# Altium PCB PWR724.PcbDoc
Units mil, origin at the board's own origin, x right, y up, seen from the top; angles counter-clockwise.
Board outline 2700 x 2000 mil, 2 copper layers (Top Layer, Bottom Layer), stack 62 mil thick; 55 components, 31 nets, 127 pads, 0 vias.
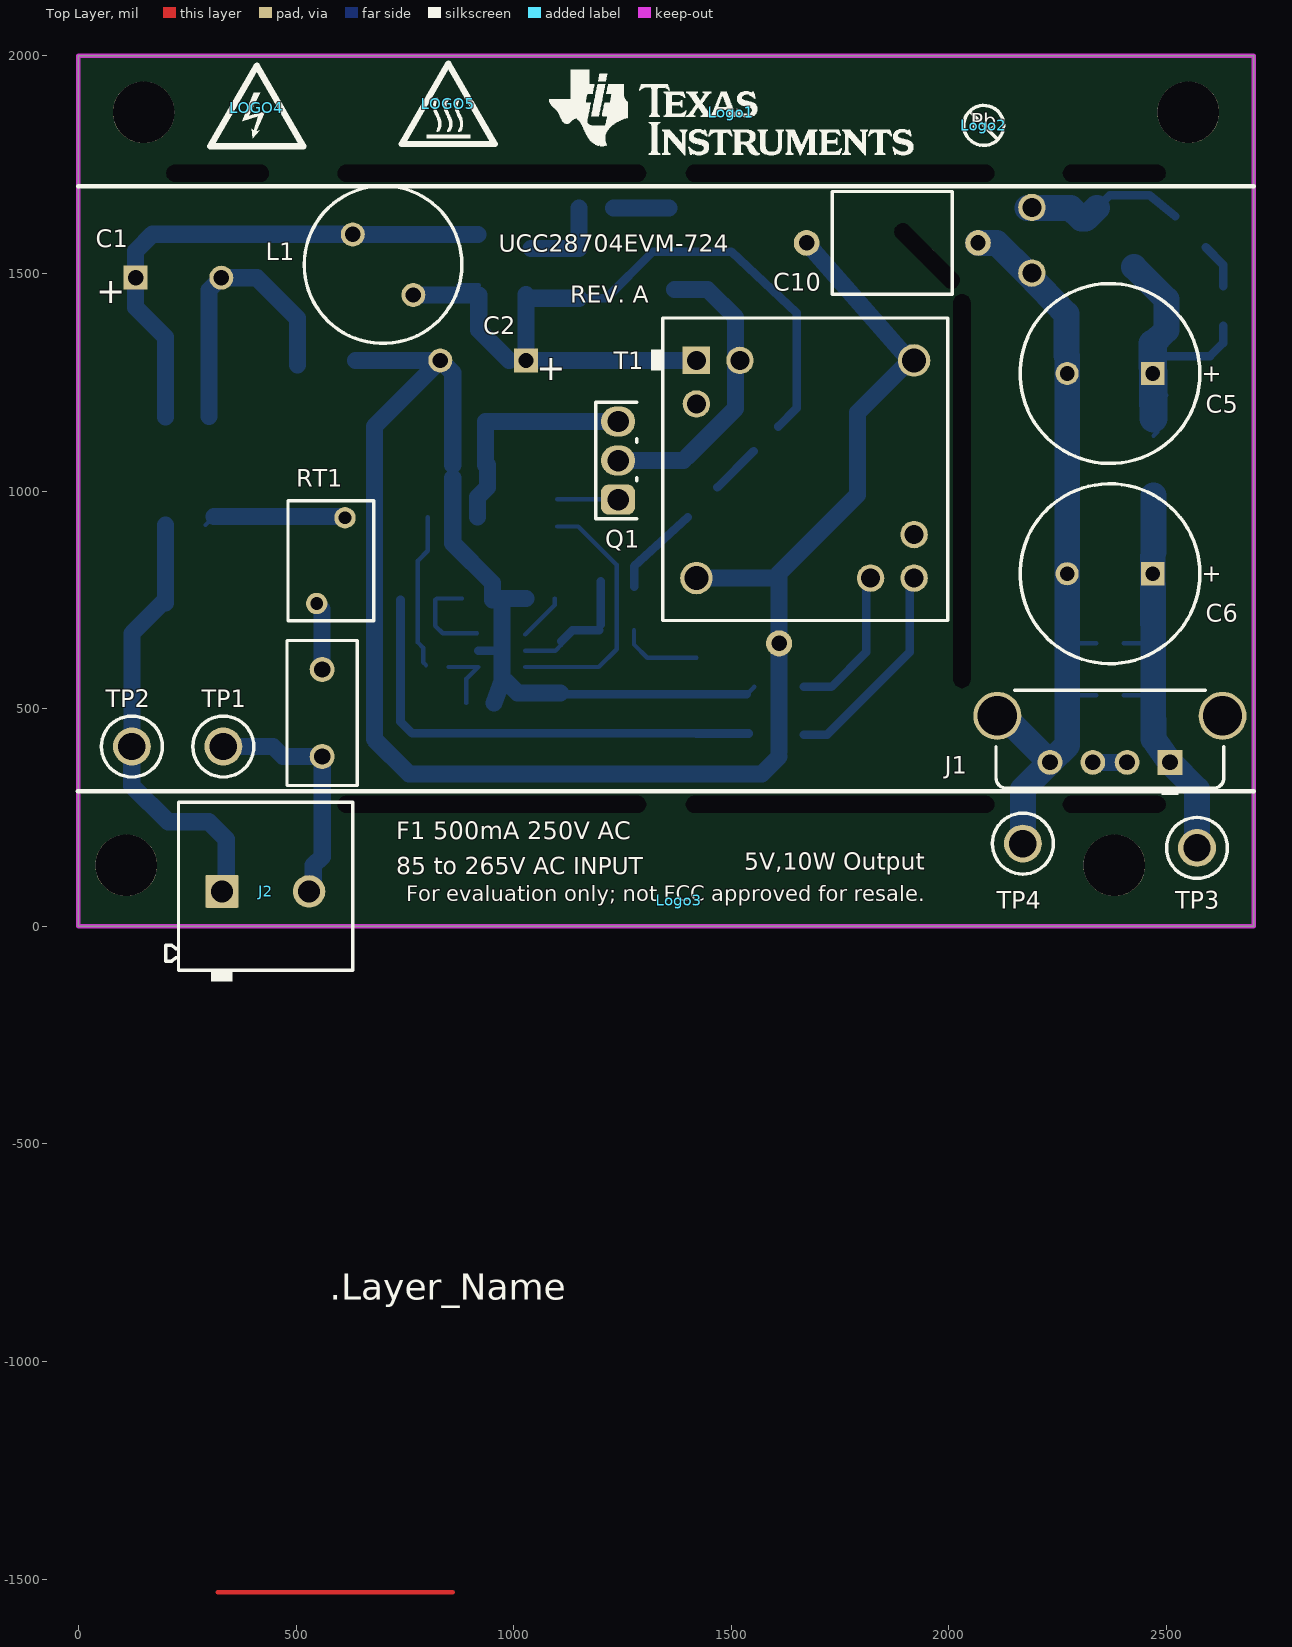
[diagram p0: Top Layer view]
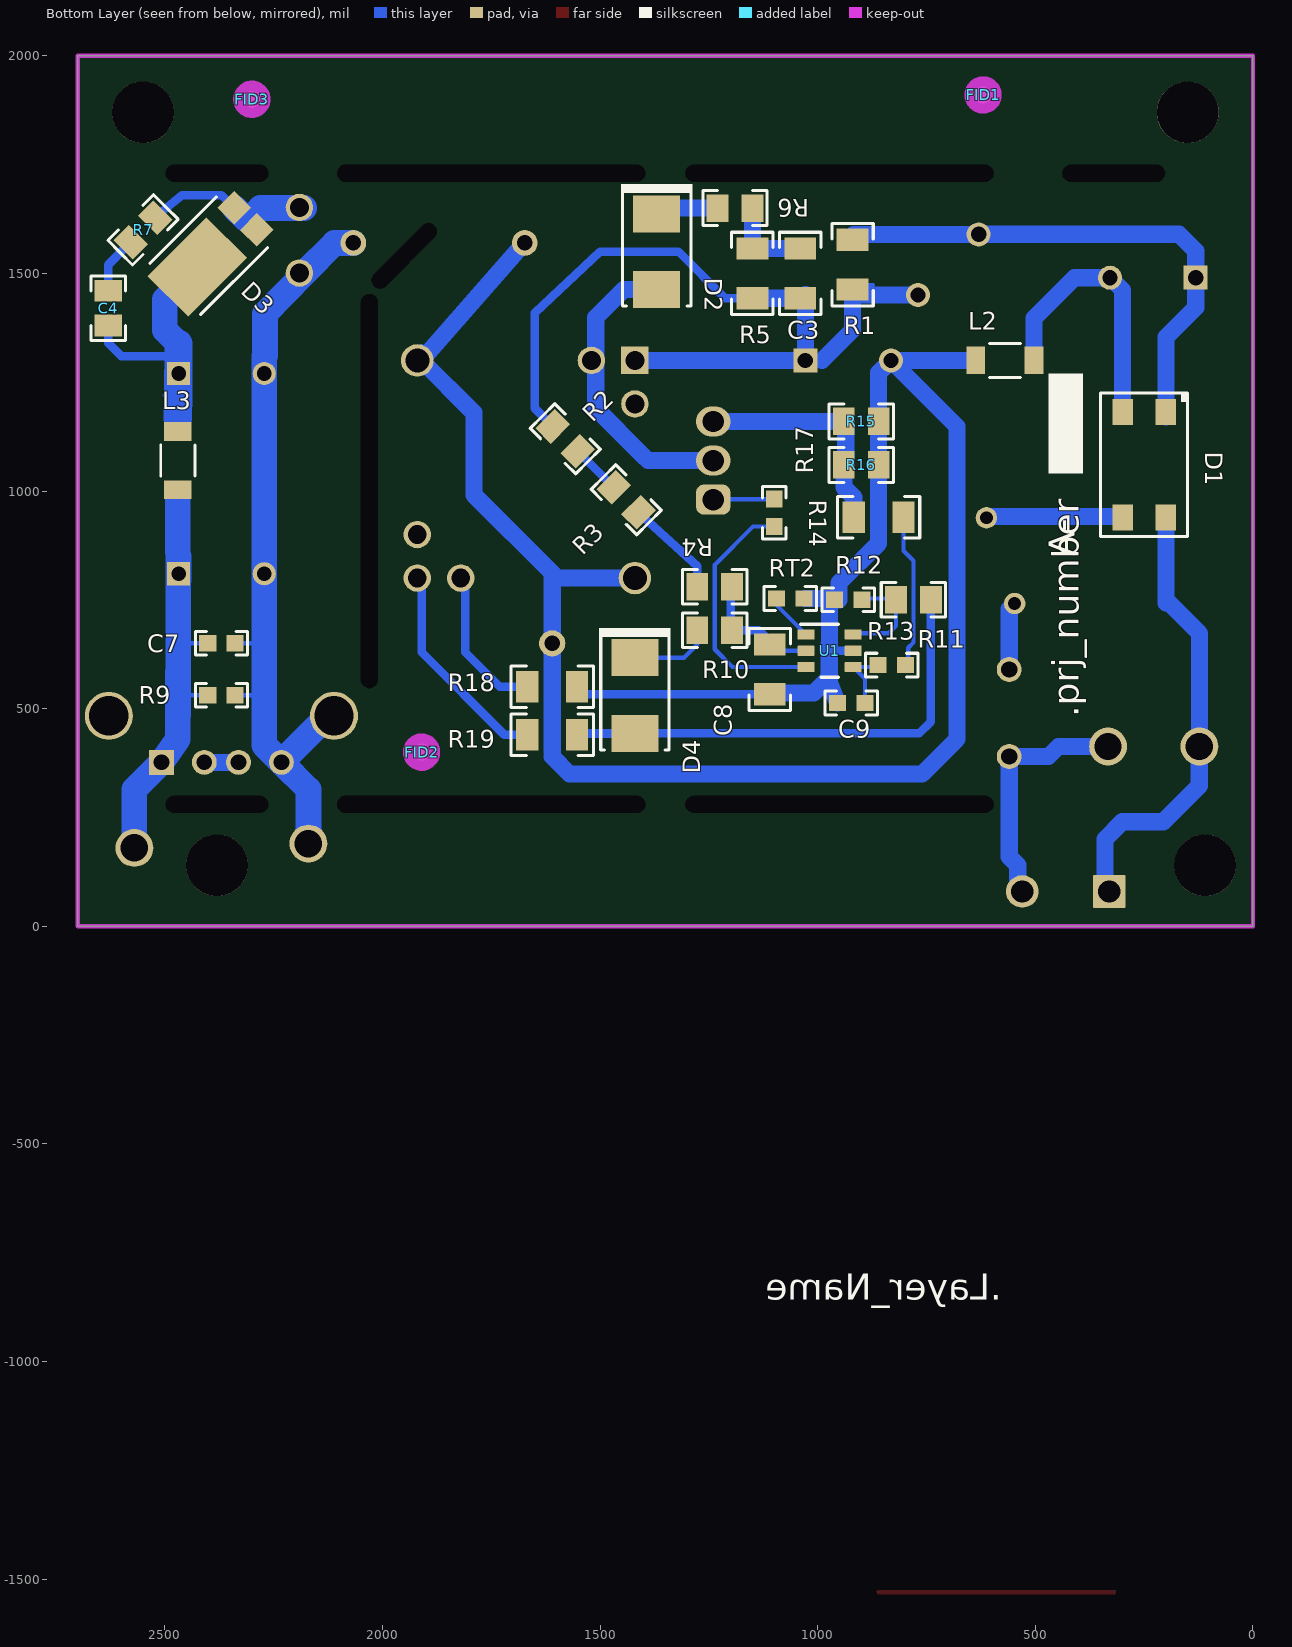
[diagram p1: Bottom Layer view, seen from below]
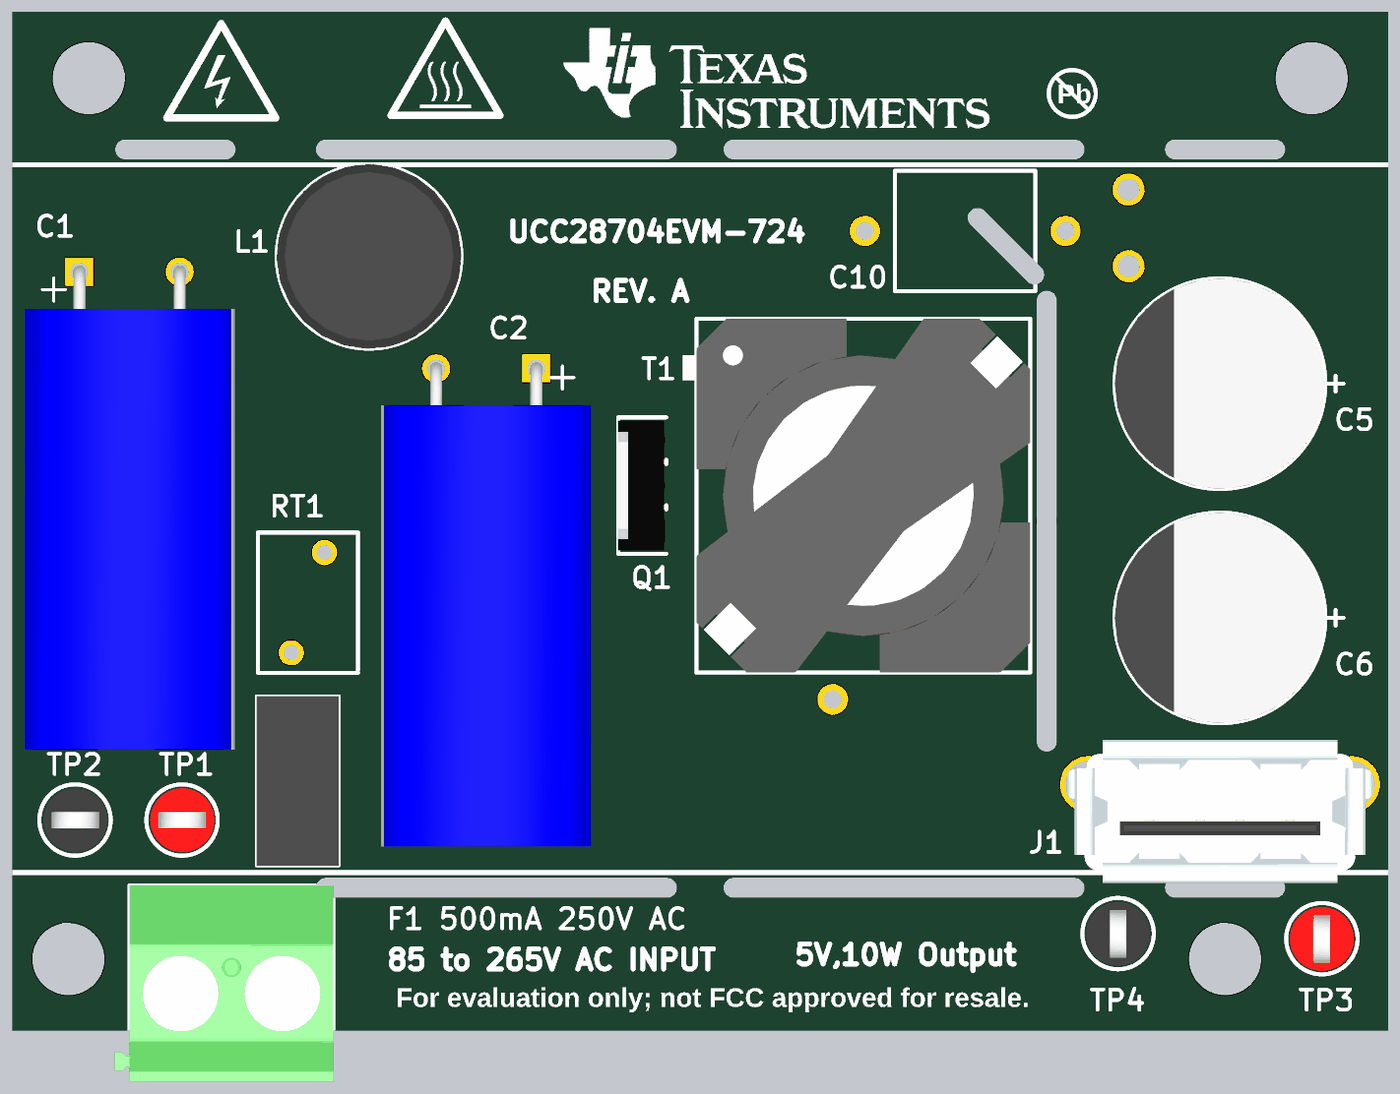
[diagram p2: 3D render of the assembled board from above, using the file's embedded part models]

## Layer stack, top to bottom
Top Solder: solder mask 0.4, Solder Resist, Dk 3.5
Top Layer: signal copper 2.8
Dielectric1: core 56.4, FR-4, Dk 4.8
Bottom Layer: signal copper 2.8
Bottom Solder: solder mask 0.4, Solder Resist, Dk 3.5

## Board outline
0,0 0,2000 2700,2000 2700,0

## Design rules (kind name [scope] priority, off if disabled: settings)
AcuteAngle [All] p1: minimum=4.50000000000000E+0001 checktracksonly=FALSE
AssemblyTestPointUsage [All] p1: valid=2
Clearance Clearance_Keepouts [((IsTrack Or IsArc) And Not InPoly) And IsFree and IsKeepOut vs ((IsTrack Or IsArc) And Not InPoly) And IsFree and IsKeepOut] p1: gap=0
Clearance Clearance_BoardEdge_MountingHoles [OnCopper and InComponentClass('Mounting Holes') vs IsKeepOut] p2: gap=40
Clearance Clearance_BoardEdge_Poly [OnCopper and InPoly vs IsKeepOut] p3: gap=25
Clearance Clearance_BoardEdge [OnCopper and Not InComponentClass('Logo') and not InComponentClass('FiducialMark') and not InRegion(1000,500,4000,800) and Not IsKeepout vs IsKeepOut] p4: gap=13.5
Clearance Clearance_Poly [InPolygon] p5: gap=25
Clearance [All] p6: gap=7.87
ComponentClearance ComponentClearance_MountingHoles_FiducialMarks [InComponentClass('Mounting Holes') vs InComponentClass('FiducialMark')] p1: gap=50 collisioncheckmode=3 verticalgap=10 showdistances=FALSE
ComponentClearance ComponentClearance_Shunt [InComponentClass('Header') vs InComponentClass('Shunt')] p2: gap=0 collisioncheckmode=3 verticalgap=0 showdistances=FALSE
ComponentClearance ComponentClearance_Logo [InComponentClass('Logo')] p3: gap=50 collisioncheckmode=3 verticalgap=10 showdistances=FALSE
ComponentClearance ComponentClearance_ScrewToNut [(HasFootprint('NY PMS 440 0025 PH')) vs (HasFootprint('Keystone_1902C'))] p4: gap=5 collisioncheckmode=3 verticalgap=10 showdistances=FALSE
ComponentClearance ComponentClearance_MountingHoles [InComponentClass('Mounting Holes')] p5: gap=250 collisioncheckmode=3 verticalgap=100000 showdistances=FALSE
ComponentClearance ComponentClearance_SmallPassives [HasFootprint('0201*') or HasFootprint('0402*') or HasFootprint('0508') or HasFootprint('0603*') or HasFootprint('0612') or HasFootprint('0805*') or HasFootprint('0815*') or HasFootprint('0830*') or HasFootprint('1206*') or HasFootprint('1210*') or HasFootprint('1808*') or HasFootprint('1812*') or HasFootprint('1825*') or HasFootprint('2010*') or HasFootprint('2220*') or HasFootprint('2225*') or HasFootprint('2512*') or HasFootprint('2728*') or HasFootprint('3518*') vs HasFootprint('0201*') or HasFootprint('0402*') or HasFootprint('0508') or HasFootprint('0603*') or HasFootprint('0612') or HasFootprint('0805*') or HasFootprint('0815*') or HasFootprint('0830*') or HasFootprint('1206*') or HasFootprint('1210*') or HasFootprint('1808*') or HasFootprint('1812*') or HasFootprint('1825*') or HasFootprint('2010*') or HasFootprint('2220*') or HasFootprint('2225*') or HasFootprint('2512*') or HasFootprint('2728*') or HasFootprint('3518*')] p6: gap=20 collisioncheckmode=3 verticalgap=10 showdistances=FALSE
ComponentClearance ComponentClearance_THtoSMT [IsThruComponent vs IsSMTComponent] p7: gap=100 collisioncheckmode=3 verticalgap=30 showdistances=FALSE
ComponentClearance ComponentClearance_THtoTH [IsThruComponent vs IsThruComponent] p8: gap=33 collisioncheckmode=3 verticalgap=30 showdistances=FALSE
ComponentClearance [All] p9: gap=40 collisioncheckmode=3 verticalgap=10 showdistances=FALSE
DiffPairsRouting [All] p1: maxlimit=100 minlimit=10 mostfreqgap=10 toplayer_minwidth=15 toplayer_maxwidth=15 toplayer_prefwidth=15 bottomlayer_minwidth=15 bottomlayer_maxwidth=15 bottomlayer_prefwidth=15 maxuncoupledlength=1000
FabricationTestPointUsage TestPointUsage [All] p1: valid=2 allowmultiple=FALSE
FabricationTestpoint Testpoint [All] p1: side=3 testpointundercomponent=TRUE minsize=40 maxsize=100 preferedsize=60 minholesize=0 maxholesize=40 preferedholesize=32 testpointgrid=1 allowsidetop=TRUE allowsidebottom=TRUE usegrid=TRUE gridtolerance=0.01
FanoutControl Fanout_LCC [IsLCC] p1: bgadir=Out bgaviamode=Centered fanoutstyle=Auto fanoutdirection=Alternating viagrid=1 // Fanout_LCC (Default Rule)
FanoutControl Fanout_BGA [IsBGA] p2: bgadir=Out bgaviamode=Centered fanoutstyle=Auto fanoutdirection=Alternating viagrid=1 // Fanout_BGA (Default Rule)
FanoutControl Fanout_Default [All] p4: bgadir=Out bgaviamode=Centered fanoutstyle=Auto fanoutdirection=Alternating viagrid=1 // Fanout_Default (Default Rule)
FanoutControl Fanout_Small [(CompPinCount < 5)] p5: bgadir=Out bgaviamode=Centered fanoutstyle=Auto fanoutdirection=OutThenIn viagrid=1 // Fanout_Small (Default Rule)
HoleSize [All] p1: absolutevalues=TRUE maxlimit=906 minlimit=8 maxpercent=80.000 minpercent=20.000
MinimumAnnularRing MinimumAnnularRing_ThermalPadVias [IsVia and InAnyComponent] p1: minimumring=5.91
MinimumAnnularRing [All] p2: minimumring=9
MinimumSolderMaskSliver MinimumSolderMaskSliver_Logo [InComponentClass('Logo') vs InComponentClass('Logo')] p1: minsoldermaskwidth=0.7
MinimumSolderMaskSliver [All] p2: minsoldermaskwidth=3.94
PlaneConnect [All] p1: planeconnectstyle=Relief reliefexpansion=10 reliefentries=4 reliefconductorwidth=10 reliefairgap=10
PolygonConnect [All] p1: connectstyle=Relief reliefconductorwidth=10 reliefentries=4 polygonreliefangle="90 Angle" airgapwidth=10
RoutingVias ThermalPadVias [IsVia and InAnyComponent] p1: holewidth=7.87 width=19.68 viastyle="Through Hole" minholewidth=7.87 minwidth=19.68 maxholewidth=12.99 maxwidth=23.62
RoutingVias [All] p2: holewidth=16 width=34 viastyle="Through Hole" minholewidth=7.87 minwidth=26 maxholewidth=40 maxwidth=65
SilkToBoardRegionClearance [Not ((IsComment or IsDesignator) And (Hide <> 'False')) and not InRegion(1000,500,4000,800)] p1:
SilkToSilkClearance SilkToSilkClearance_Pb-FreeLogo [(HasFootprint('Pb-Free_Overlay_Medium') OR HasFootprint('Pb-Free_Overlay_Small')) vs (HasFootprint('Pb-Free_Overlay_Medium') OR HasFootprint('Pb-Free_Overlay_Small'))] p1: silktosilkclearance=0
SilkToSilkClearance [All] p2: silktosilkclearance=4
SilkToSolderMaskClearance SilkToComonentPadClearance [IsPad and InAnycomponent] p1: minsilkscreentomaskgap=5 clearancetoexposedcopper=TRUE
SilkToSolderMaskClearance "Silk to Solder Mask Opening" [All] p2: minsilkscreentomaskgap=4 clearancetoexposedcopper=FALSE
SolderMaskExpansion [All] p1: expansion=1.97
UnpouredPolygon [All] p1: allowunpoured=FALSE
Width [All] p1: maxlimit=100 minlimit=6 preferedwidth=10 checkconnectedcopper=TRUE
14 further rules are at their usual default settings.

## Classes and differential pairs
component class FiducialMark: FID1 FID2 FID3
component class Logo: Logo1
component class PWR724_Hardware: !PCB FID1 FID2 FID3 Logo1 Logo2 Logo3 LOGO4 LOGO5

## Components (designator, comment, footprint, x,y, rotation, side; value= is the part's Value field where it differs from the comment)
C1 "UCS2G100MPD1TD" CAPPRD500W60D1000H2000_Horizontal_DOWN 230,1490 r0 top
C2 "UCS2G100MPD1TD" CAPPRD500W60D1000H2000_Horizontal_UP 930,1300 r180 top
C3 "GRM31A7U2J471JW31D" 1206 1040,1500 r90 bottom
C4 "08055A101JAT2A" 0805_HV 2630,1420 r90 bottom
C5 "PLF1C471MDO1" LF_1000x1300 2370,1270 r180 top
C6 "PLF1C471MDO1" LF_1000x1300 2370,810 r180 top
C7 "C1608X7R1E105K080AB" 0603 2370,650 r180 bottom
C8 "GRM319R71H334KA01D" 1206 1110,590.07 r270 bottom
C9 "06035A270JAT2A" 0603 923.01,513.07 r0 bottom
C10 "CD70-B2GA101KYNKA" CD_700x1100x700 1870,1570 r180 top
D1 "HD06-T" MiniDIP 250,1060 r270 bottom
D2 "MURS160-13-F" SMB 1370,1550 r270 bottom
D3 "SBRT15U50SP5-13" PowerDI5 2370,1570 r315 bottom
D4 "MURS160-13-F" SMB 1420,530 r270 bottom
"F1 500mA 250V AC" "RST 500" Fuse_RST 560,490 r270 top (schematic designator F1)
FID1 "Fiducial" Fiducial10-20 620,1910 r180 bottom
FID2 "Fiducial" Fiducial10-20 1910,400 r270 bottom
FID3 "Fiducial" Fiducial10-20 2300,1900 r270 bottom
J1 "923" Keystone_923 2370,430 r180 top
J2 "1715721" PhoenixContact_1715721 430,80 r0 top
L1 "RLB0914-471KL" RLB0914 700,1520 r315 top
L2 "742792121" 1206_190 570,1300 r0 bottom
L3 "742792121" 1206_190 2470,1070 r270 bottom
Logo1 "Texas Instruments" TI_Stacked_Overlay_Small 1500,1870 r0 top
Logo2 "Pb-Free Symbol" Pb-Free_Overlay_Small 2080,1840 r0 top
Logo3 "FCC disclaimer" FCC_disclaimer 1380,60 r0 top
LOGO4 "DANGER HIGH VOLTAGE" IEC_HighVoltage_Small 410,1880 r0 top
LOGO5 "CAUTION HOT SURFACE" IEC_HotSurface_Small 850,1890 r0 top
Q1 "STU7NM60N" IPAK 1240,1070 r90 top
R1 "CRCW12061K00FKEA" 1206 920,1520 r90 bottom
R2 "CRCW08055M11FKEA" 0805_HV 1580,1120 r45 bottom
R3 "CRCW08055M11FKEA" 0805_HV 1440,980 r45 bottom
R4 "CRCW08055M11FKEA" 0805_HV 1236.69,780 r0 bottom
R5 "CRCW1206511KFKEA" 1206 1150,1500 r270 bottom
R6 "CRCW080551R1FKEA" 0805_HV 1190,1650 r0 bottom
R7 "CRCW0805510KJNEA" 0805_HV 2550,1600 r315 bottom
R9 "CRCW06031K00FKEA" 0603 2370,531.08 r0 bottom
R10 "CRCW080520R0JNEA" 0805_HV 1236.69,680 r0 bottom
R11 "CRCW0805115KFKEA" 0805_HV 780,750.07 r180 bottom
R12 "CRCW060336K5FKEA" 0603 930,750 r180 bottom
R13 "RC0603FR-07715RL" 0603 830,600.07 r180 bottom
R14 "MCR18EZHJ000" 1206 860,940 r0 bottom
R15 "CRCW08052R15FKEA" 0805_HV 900,1160 r0 bottom
R16 "CRCW08052R15FKEA" 0805_HV 900,1060 r0 bottom
R17 "CRCW060310R0JNEAHP" 0603 1100,950 r90 bottom
R18 "MCR18EZHJ000" 1206 1610,550 r0 bottom
R19 "MCR18EZHJ000" 1206 1610,440 r0 bottom
RT1 "MF72-005D5" MF72D5 580,840 r90 top
RT2 "NTCG164KF104F" 0603 1063.01,753.07 r0 bottom
T1 "750315841" Wurth_750315841 1670,1050 r0 top
TP1 "5010" Keystone5010 333.01,413 r90 top
TP2 "5011" Keystone5011 123.01,413 r90 top
TP3 "5010" Keystone5010 2570,180 r0 top
TP4 "5011" Keystone5011 2170,190 r0 top
U1 "UCC28704DBVR-1" DBV0006A_N 972.7,633.07 r180 bottom

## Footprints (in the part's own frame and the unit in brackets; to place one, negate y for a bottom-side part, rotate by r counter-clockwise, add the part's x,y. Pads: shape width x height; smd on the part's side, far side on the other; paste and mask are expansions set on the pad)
0603 [mm] "0603 from SM-752 data"
  rect 1x0.95 smd: 1(-0.8,0) 2(0.8,0)
  silkscreen extent -1.52,-0.69 1.52,0.69, body extent -0.87,-0.47 0.87,0.47, height 1
0805_HV [mil] "0805 with 30mil clearance between pads"
  rect 50x63 smd: 1(-40,0) 2(40,0)
  silkscreen extent -74,-40 74,40, body extent -43,-29 43,29, height 57
1206 [mm] "1206 from SM-752 data"
  rect 1.3x1.85 smd: 1(-1.45,0) 2(1.45,0)
  silkscreen extent -2.4,-1.21 2.4,1.21, body extent -1.7,-0.9 1.7,0.9, height 1.35
1206_190 [mm] "1206_190"
  rect 1.1x1.6 smd: 1(-1.7,0) 2(1.7,0)
  silkscreen extent -0.9,-1 0.9,1, body extent -1.75,-0.95 1.75,0.95, height 1.9
CAPPRD500W60D1000H2000_Horizontal_DOWN [mm] "Nichicon"
  rect 1.4x1.4 hole 0.889: 1(-2.5,0)
  round 1.4 hole 0.889: 2(2.5,0)
  body extent -5.21,-23.85 5.24,0.3, height 10.49
CAPPRD500W60D1000H2000_Horizontal_UP [mm] "Nichicon"
  rect 1.4x1.4 hole 0.889: 1(-2.5,0)
  round 1.4 hole 0.889: 2(2.5,0)
  body extent -5.21,-0.3 5.23,23.85, height 10.49
CD_700x1100x700 [mm] "TDK"
  round 1.5 hole 0.9: 1(-5,0) 2(5,0)
  silkscreen extent -3.5,-3 3.5,3, body extent -5.3,-3 5.3,2.98, height 10.49
DBV0006A_N [mm] "SOT23, 6-Leads, Body 2.9x1.6mm, Pitch 0.95mm, Lead Span 2.8mm, IPC Medium Density"
  rrect17% 1x0.6 smd: 1(-1.375,0.95) 2(-1.375,0) 3(-1.375,-0.95) 4(1.375,-0.95) 5(1.375,0) 6(1.375,0.95)
  silkscreen extent -1.68,-1.55 0.5,1.55, body extent -1.42,-1.46 1.42,1.46, height 1.12
FCC_disclaimer [mil]
Fiducial10-20 [mm]
  round 1 smd mask+0.5: 1(0,0)
  Top Layer keep-out circle w1.178: c0,0 r0.5
Fuse_RST [mm] "Bel Fuse RST series May2012D"
  round 1.45 hole 0.95: 1(-2.54,0) 2(2.54,0)
  silkscreen extent -4.23,-2.05 4.23,2.05, body extent -4.22,-2.05 4.23,2.05, height 7.9
IEC_HighVoltage_Small [mil]
  silkscreen extent -107,-88 107,97
IEC_HotSurface_Small [mil]
  silkscreen extent -107,-93 107,92
IPAK [mm] "IPAK"
  rrect50% 1.75x2 hole 1.25: 1(-2.28,0)
  oval 1.75x2 hole 1.25: 2(0,0) 3(2.28,0)
  silkscreen extent -3.4,-1.1 3.4,1.3, body extent -3.25,-0.99 3.25,1.31, height 9.66
Keystone5010 [mil] "Keystone Multipurpose loops"
  round 87 hole 63: 1(0,0)
  silkscreen extent -70,-70 70,70, body extent -63,-63 63,62, height 319
Keystone5011 [mil] "Keystone Multipurpose loops"
  round 87 hole 63: 1(0,0)
  silkscreen extent -70,-70 70,70, body extent -63,-63 63,62, height 319
Keystone_923 [mm] "Connector, Receptacle, USB Type A, Vertical, TH"
  rect 1.45x1.45 hole 0.92: 1(-3.5,1.355)
  round 1.45 hole 0.92: 2(-1,1.355) 3(1,1.355) 4(3.5,1.355)
  round 2.8 hole 2.3: S1(-6.57,-1.355) S2(6.57,-1.355)
  silkscreen extent -6.65,-2.86 6.65,3.25, body extent -7.65,-3.56 7.65,3.56, height 14.38
LF_1000x1300 [mm] "THD, 2-Leads, 10 mm Dia, Height 13 mm, Pin Spacing 5 mm"
  rect 1.35x1.35 hole 0.85: 1(-2.5,0)
  round 1.35 hole 0.85: 2(2.5,0)
  silkscreen extent -5.25,-5.25 5.25,5.25, body extent -5.25,-5.24 5.25,5.24, height 13.51
MF72D5 [mm] "TH, 2-Leads, Dia 7mm"
  round 1.25 hole 0.75: 1(-2.5,0.825) 2(2.5,-0.825)
  silkscreen extent -3.5,-2.5 3.5,2.5, body extent -3.52,-2.5 3.48,2.5, height 11
MiniDIP [mm] "Land pattern created based on STEP model."
  rect 1.52x1.2 smd: 1(-3.075,1.25) 2(-3.075,-1.25) 3(3.075,-1.25) 4(3.075,1.25)
  silkscreen extent -4.19,-2.54 4.19,2.54, body extent -3.5,-2.45 3.5,2.45, height 2.75
Pb-Free_Overlay_Small [mil]
  silkscreen extent -46,-46 46,46
PhoenixContact_1715721 [mm] "Phoenix Contact 1715721 used on LM3445 design from Longmont"
  rrect5% 1.905x1.905 hole 1.3: 1(-2.54,0)
  round 1.9 hole 1.3: 2(2.54,0)
  silkscreen extent -5.82,-5.25 5.08,5.2, body extent -5.82,-4.6 5.08,5.2, height 14.2
PowerDI5 [mm] "Diodes Inc recommended land pattern, ap02001.pdf rev 60"
  rect 1.4x1.39 smd: 1(-1.991,0.92) 2(-1.991,-0.92)
  rect 4.86x3.36 smd: 3(1.991,0)
  silkscreen extent -1.7,-2.1 3.8,2.1, body extent -2.27,-2.02 4.33,2.03, height 1.17
RLB0914 [mm] "TH, 2-Leads, Dia 8.7mm, Pin Spacing 5mm"
  round 1.4 hole 0.9: 1(-2.5,0) 2(2.5,0)
  silkscreen extent -4.6,-4.6 4.6,4.6, body extent -4.6,-4.6 4.6,4.6, height 13
SMB [mil] "Molded Diode, 2-Leads, Body 5.4x3.6mm, IPC Medium Density, based on OnSemi component dimensions"
  rect 85x107.99 smd: 1(-87.01,0) 2(87.01,0)
  silkscreen extent -155,-82 125,82, body extent -106,-71 106,71, height 91
TI_Stacked_Overlay_Small [mil]
  silkscreen extent -418,-98 418,98
Wurth_750315841 [mm] "TH, 6-Leads, Body 16.64x17.65mm"
  rect 1.6x1.6 hole 1.1: 1(-6.35,6.35)
  round 1.6 hole 1.1: 2(-6.35,3.81) 3(3.81,-6.35) 4(6.35,-6.35) 5(6.35,-3.81) 6(-3.81,6.35) FL1(13.225,11.45) FL2(13.225,15.275)
  round 1.9 hole 1.4: MH1(6.35,6.35) MH2(-6.35,-6.35)
  silkscreen extent -9,-8.82 8.32,8.82, body extent -8.32,-8.82 8.32,8.83, height 13.21

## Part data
C1 C2: "CAP, AL, 10 µF, 400 V, +/- 20%, TH"
C3: "CAP, CERM, 470 pF, 630 V, +/- 5%, U2J, 1206"
C4: "CAP, CERM, 100 pF, 50 V, +/- 5%, C0G/NP0, 0805"
C5 C6: "CAP, AL, 470 µF, 16 V, +/- 20%, 0.009 ohm, TH"
C7: "CAP, CERM, 1 µF, 25 V, +/- 10%, X7R, 0603"
C8: "CAP, CERM, 0.33 µF, 50 V, +/- 10%, X7R, 1206"
C9: "CAP, CERM, 27 pF, 50 V, +/- 5%, C0G/NP0, 0603"
C10: "CAP, CERM, 100 pF, 440 V, +/- 10%, B, 7.0x11.0x7.0mm"
D1: "Diode, Switching-Bridge, 600 V, 0.8 A, MiniDIP"
D2 D4: "Diode, Ultrafast, 600 V, 1 A, SMB"
D3: "Diode, Super Barrier Rectifier, 50 V, 15 A, AEC-Q101, PowerDI5"
"F1 500mA 250V AC": "Fuse, 0.5 A, 250VAC/VDC, TH"
FID1 FID2 FID3: "Fiducial mark.  There is nothing to buy or mount."
J1: "Connector, Receptacle, USB Type A, Vertical, TH"
J2: "Terminal Block, 5.08 mm, 2x1, TH"
L1: "Inductor, Wirewound, Ferrite, 470 µH, 0.5 A, 1.3 ohm, TH"
L2 L3: "Ferrite Bead, 300 ohm @ 100 MHz, 3 A, 1206_190"
Logo1: library part TI_Logo, "Texas Instrument Corporate Signature"
Logo2: library part Pb-Free
Logo3: library part FCC_disclaimer, "FCC_disclaimer"
LOGO4: library part IEC_HighVoltage, "IEC 61010-1 High Voltage Warning"
LOGO5: library part IEC_HotSurface, "IEC 61010-1 Hot Surface Warning"
Q1: "MOSFET, N-CH, 600 V, 5 A, IPAK"
R1: "RES, 1.00 k, 1%, 0.25 W, 1206"
R2 R3 R4: "RES, 5.11 M, 1%, 0.125 W, 0805"
R5: "RES, 511 k, 1%, 0.25 W, 1206"
R6: "RES, 51.1, 1%, 0.125 W, 0805"
R7: "RES, 510 k, 5%, 0.125 W, 0805"
R9: "RES, 1.00 k, 1%, 0.1 W, 0603"
R10: "RES, 20, 5%, 0.125 W, 0805"
R11: "RES, 115 k, 1%, 0.125 W, 0805"
R12: "RES, 36.5 k, 1%, 0.1 W, 0603"
R13: "RES, 715, 1%, 0.1 W, 0603"
R14 R18 R19: "RES, 0, 5%, 0.25 W, 1206"
R15 R16: "RES, 2.15, 1%, 0.125 W, 0805"
R17: "RES, 10, 5%, 0.25 W, 0603"
RT1: "Thermistor NTC, 5 ohm, 20%, MF72D5 TH"
RT2: "Thermistor NTC, 100k ohm, 1%, 0603"
T1: "Transformer, 750 uH, TH"
TP1 TP3: "Test Point, Multipurpose, Red, TH"
TP2 TP4: "Test Point, Multipurpose, Black, TH"
U1: "CV/CC Flyback Controller with Primary-Side Regulation (PSR) and CC Under-Voltage Protection, DBV0006A"

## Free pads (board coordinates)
  round 141.73 hole 141.73 unplated: 0(110,140) 0(150,1870) 0(2380,140) 1(2550,1870)
  round 35.43 hole 39.37 slot 236.22 at 0 deg unplated: 0(320,1730) 0(2380,280) 0(2380,1730)
  round 35.43 hole 39.37 slot 708.66 at 0 deg unplated: 0(950,280) 0(950,1730) 1(1750,280) 1(1750,1730)
  round 60 hole 35.43: 0(1610,650)
  round 39.37 hole 39.37 slot 196.85 at 135 deg unplated: 0(1950,1540)
  round 39.37 hole 39.37 slot 905.51 at 90 deg unplated: 0(2030,1000)

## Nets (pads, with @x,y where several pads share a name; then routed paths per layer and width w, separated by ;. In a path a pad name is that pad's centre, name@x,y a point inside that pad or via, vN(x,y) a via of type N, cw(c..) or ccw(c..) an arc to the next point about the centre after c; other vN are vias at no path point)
NetC1_1: C1.1 D1.1 L1.1 R1.2 | length 1233.2
  Bottom Layer w10: C1.1@134.59,1493 C1.1@134.59,1514.57 ; L1.1@630,1590 L1.1
  Bottom Layer w39.37: D1.1@200,1170.26 200,1353.15 131.57,1421.57 C1.1 131.57,1551.57 170,1590 L1.1@630,1590 ; L1.1 R1.2@917.49,1589.6
NetC1_2: C1.2 D1.2 L2.1 | length 650.1
  Bottom Layer w39.37: D1.2@300,1171.84 300,1461.57 C1.2 410,1490 503.07,1396.93 L2.1@503.07,1290
NetC2_1: C2.1 C3.1 L1.2 R1.1 R2.2 R5.2 T1.1 | length 1965.6
  Bottom Layer w10: 872.91,1472.91 R1.1@920,1472.91 ; R1.1@920,1450.4 R1.1 ; 990,1300 C2.1
  Bottom Layer w19.68: R5.2 1212.91,1442.91 1320,1550 1500,1550 1650,1410 1650,1190 R2.2
  Bottom Layer w39.37: L1.2 920,1450.4 920,1370 990,1300 ; C3.1@1028.43,1431.34 C3.1 R5.2 ; C3.1@1028.43,1451.34 C2.1 T1.1@1410,1300
NetC3_2: C3.2 R5.1 R6.1 | length 202.9
  Bottom Layer w39.37: C3.2 R5.1 R6.1
NetC4_1: C4.1 C5.1 D3.3 L3.1 | length 701.1
  Bottom Layer w10: 2468.43,1310 2468.43,1338.43 ; 2469.42,1219.77 2499.77,1219.77 ; L3.1@2470,1127.09 L3.1@2478.43,1135.51 ; L3.1@2470,1147.09 2470,1160 2478.43,1168.43
  Bottom Layer w19.68: 2468.43,1310 2600,1310 2630,1340 C4.1
  Bottom Layer w59.06: D3.3 2500,1440 2500,1370 2468.43,1338.43
  Bottom Layer w64.96: 2468.43,1338.43 2469.42,1219.77 2470,1166.93
NetC4_2: C4.2 R7.2 | length 106.6
  Bottom Layer w19.68: R7.2@2590,1560 2630,1520 C4.2@2630,1470
NetC6_1: C6.1 C7.1 J1.1 L3.2 R9.2 TP3.1 | length 975.2
  Bottom Layer w10: R9.2 2468.58,531.08 2469.62,530.04 ; C7.1 2469.14,650 ; 2468.88,729.96 2470.04,729.96
  Bottom Layer w59.06: 2468.43,850 2468.88,729.96 2469.18,650.03 2469.62,530.04 2470,430 J1.1 2570,314.45 TP3.1 ; 2470,860 L3.2@2470,990
NetC8_1: C8.1 R4.1 R10.1 U1.2 | length 297.9
  Bottom Layer w10: U1.2 1095.91,633.07 C8.1 C8.1@1110,654.8 ; R10.1@1196.79,690.09 R10.1@1199.71,693
  Bottom Layer w19.68: C8.1@1110,654.8 1135.2,680 R10.1 ; R10.1@1199.71,693 R4.1@1199.71,793
NetC9_1: C9.1 R13.1 U1.4 | length 162
  Bottom Layer w10: R13.1@850.41,595.67 U1.4 891.52,568.62 C9.1
NetD1_3: D1.3 RT1.2 | length 331.3
  Bottom Layer w10: D1.3@292.23,921.94 D1.3@311.71,941.43
  Bottom Layer w39.37: D1.3@311.71,941.43 RT1.2@615.49,941.43
NetD1_4: D1.4 J2.1 TP2.1 | length 1016.2
  Bottom Layer w39.37: TP2.1 123.01,673 193.8,743.79 ; 200,743.07 D1.4@200,921.22
  Bottom Layer w40: TP2.1 123.01,323.01 206.03,240 300,240 340,200 J2.1@340,80
NetD2_1: D2.1 R6.2 | length 127
  Bottom Layer w39.37: R6.2 D2.1@1357.01,1650
NetD2_2: D2.2 Q1.2 T1.6 | length 690.8
  Bottom Layer w39.37: Q1.2@1230,1070 1390,1070 ; D2.2 1445.51,1462.99 1510,1398.5 1510,1300 1510,1190 1400,1080
NetD3_1: D3.1 D3.2 R7.1 T1.FL2 | length 390.1
  Bottom Layer w10: 2304.57,1625.43 2314.57,1625.43 ; D3.2 D3.2@2341.04,1651.04
  Bottom Layer w19.68: D3.2@2341.04,1651.04 2370,1680 2460,1680 R7.1@2520,1631.25
  Bottom Layer w59.06: T1.FL2@2180,1650 2280,1650 2304.57,1625.43 ; 2314.57,1625.43 D3.2
NetD4_1: D4.1 R10.2 | length 188.5
  Bottom Layer w10: R10.2 1276.69,647.32 1307.01,617.01 D4.1
NetD4_2: D4.2 R11.2 R19.1 | length 1091.1
  Bottom Layer w19.68: R11.2 740,470.07 767,443.07 D4.2 R19.1@1539.92,442.99
NetF1_1: "F1 500mA 250V AC.1" RT1.1 | length 139.1
  Bottom Layer w39.37: 560,590 RT1.1@560,729.09
NetF1_2: "F1 500mA 250V AC.2" J2.2 TP1.1 | length 554.8
  Bottom Layer w39.37: TP1.1 447,413 470,390 560,390
  Bottom Layer w40: J2.2@540,80 540,140 560,160 560,390
NetJ1_2: J1.2 J1.3 | length 78.7
  Bottom Layer w39.37: J1.3 J1.2
NetQ1_1: Q1.1 R17.2 | length 140.5
  Bottom Layer w10: R17.2 1238.74,981.5 Q1.1
NetQ1_3: Q1.3 R14.2 R15.2 R16.2 | length 529.5
  Bottom Layer w39.37: R14.2 917.09,985.67 940,1008.58 R16.2 ; R16.2@935.59,1060 R15.2@935.59,1160 ; R15.2 Q1.3
NetR2_1: R2.1 R3.2 | length 118
  Bottom Layer w19.68: R3.2 R2.1
NetR3_1: R3.1 R4.2 | length 214.2
  Bottom Layer w19.68: R4.2 1276.69,826.69 R3.1@1400,940
NetR11_1: R11.1 R12.2 U1.6 | length 225.8
  Bottom Layer w10: R12.2@881.52,753.07 823,753.07 R11.1 820,690.07 837,673.07 U1.6@915.97,673.07
NetR13_2: R13.2 R14.1 | length 357.1
  Bottom Layer w10: R13.2 791.97,606.61 791.97,640.07 780,652.04 780,840 802.91,862.91 R14.1
NetR17_1: R17.1 U1.3 | length 593.7
  Bottom Layer w10: U1.3 1195.67,595.67 1236.69,636.69 1236.69,830.31 1148.5,918.5 R17.1
NetR18_2: R18.2 T1.3 | length 346.1
  Bottom Layer w19.68: R18.2 1730,550 1810,630 T1.3@1810,800
NetR19_2: R19.2 T1.4 | length 491.6
  Bottom Layer w19.68: R19.2 1720,440 1910,630 T1.4@1910,800
NetRT2_2: RT2.2 U1.1 | length 110.6
  Bottom Layer w10: U1.1 1094.51,738.15 RT2.2
PGND: C2.2 C8.2 C9.2 C10.2 L2.2 pad.0@1610,650 R12.1 R15.1 R16.1 R18.1 RT2.1 T1.MH1 T1.MH2 U1.5 | length 5277.7
  Bottom Layer w10: C8.2@1107,535.98 C8.2 ; R18.1@1535.9,532.98 R18.1 ; 1550,350 1580,350 ; 1598.61,800 1610,811.39 ; T1.MH1@1910,1300 T1.MH1@1910,1333.15
  Bottom Layer w19.68: U1.5 973.01,633.07 ; C8.2 R18.1@1535.9,532.98
  Bottom Layer w39.37: L2.2 C2.2 ; R16.1@860,1030 860,880 951.5,788.5 R12.1@951.5,750.07 ; R16.1 R15.1 860,1271.57 C2.2 ; C9.2 973.56,563.07 R12.1@973,743.07 ; R12.1@954.51,753.07 RT2.1@1028.56,753.07 ; 983.01,562.2 1009.23,535.98 C8.2@1107,535.98 ; T1.MH2@1410,800 1598.61,800 ; 1610,390 1570,350 760,350 680,430 680,1148.43 C2.2 ; 1610,401.39 1610,811.39 1790,991.39 1790,1180 1910,1300 C10.2
SGND: C5.2 C6.2 C7.2 C10.1 J1.4 J1.S2 R9.1 T1.FL1 TP4.1 | length 1832.3
  Bottom Layer w10: J1.S2 J1.S2@2125.51,483.35 ; 2270,1311.57 2271.57,1310 ; 2271.57,530 2272.66,531.08 R9.1 ; 2271.57,650 C7.2 ; C5.2@2279.92,1271.65 C5.2@2279.92,1280
  Bottom Layer w59.06: C10.1 2110,1570 2180,1500 2270,1406.85 2270,1311.57 ; J1.S2@2125.51,483.35 J1.4 ; TP4.1 2170,314.45 J1.4 ; 2271.57,850 2271.57,650 2271.57,530 2271.57,416.02 J1.4 ; 2271.57,856.69 2271.57,1310
pads on no net: FID1.1 FID2.1 FID3.1 J1.S1 T1.2 T1.5
copper on no net: | length 540
  Top Layer w10: 320,-1530 860,-1530

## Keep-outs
Keep-Out Layer:
  the board outline again, w10
  text ".Layer_Name" at 577,-858.49 h60

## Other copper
Top Layer:
  text ".Layer_Name" at 577,-858.49 h60
Bottom Layer:
  text ".Layer_Name" at 577,-858.49 h60

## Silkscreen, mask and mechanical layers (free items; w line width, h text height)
Top Overlay:
  lines w10: -1.41,310 2700,310 ; -0.66,1700 2700,1700
  text "UCC28704EVM-724" at 966.26,1550 h39.37
  text "REV. A" at 1130,1433.07 h39.37
  text "5V,10W Output" at 1530,130 h39.37
  text "85 to 265V AC INPUT" at 730,120 h39.37
  text ".Layer_Name" at 577,-858.49 h60
Bottom Overlay:
  region: 390,1270 390,1040 470,1040 470,1270
  text "A-" at 410,850 h60 r270
  text ".prj_number" at 400,480 h60 r270
  text ".Layer_Name" at 577,-858.49 h60
Top Paste:
  text ".Layer_Name" at 577,-858.49 h60
Bottom Paste:
  text ".Layer_Name" at 577,-858.49 h60
Top Solder:
  text ".Layer_Name" at 577,-858.49 h60
  text ".Layer_Name" at 577,-858.49 h60
Bottom Solder:
  text ".Layer_Name" at 577,-858.49 h60
Drill Guide:
  text ".Layer_Name" at 577,-858.49 h60
M1 Board Outline:
  the board outline again, w10
  text ".Layer_Name" at 577,-858.49 h60
M2 Board Dimensions:
  rectangle: 125,-400 500,-275
  rectangle: 0,-275 125,-150
  lines w7: 0,-275 1000,-275 ; 125,-400 125,-150 ; 250,-400 250,-150 ; 500,-400 500,-150 ; 750,-400 750,-150 ; 0,-400 0,-150 1000,-150 1000,-400 0,-400
  text ".Layer_Name" at 577,-858.49 h60
M3 3D STEP Top:
  text ".Layer_Name" at 577,-858.49 h60
M4 3D STEP Bottom:
  text ".Layer_Name" at 577,-858.49 h60
M5 Assembly Top:
  lines w10: -292,-930.17 6308,-930.17 ; -292,-726.83 6310,-726.83 ; -292,-523.5 -292,-1133.5 3713,-1133.5 6310,-1133.5 6310,-523.5 -291.5,-523.5 -291.5,-1133.5 1284,-1133.5 ; 2173,-1133.5 2173,-523.5 ; 3440,-726.83 3440,-523.5 ; 4280,-726.83 4280,-523.5 ; 4902,-1140 4902,-937.17
  text "COMPONENTS MARKED 'DNP' SHOULD NOT BE POPULATED." at 1153.5,-318.5 h60
  text "ASSEMBLY VARIANT:" at 1153,-434 h60
  text ".VariantName" at 2189,-434 h60
  text "PCB VIEWED FROM TOP SIDE" at -228.5,-655.67 h60
  text "BOARD #:" at 2248,-655.67 h60
  text ".PRJ_Number" at 2793.5,-655.67 h60
  text "REV:" at 3638,-655.67 h60
  text ".PCB_Rev" at 3929.5,-655.67 h60
  text "SVN REV:" at 4476,-655.67 h60
  text ".VersionControl_RevNumber" at 4982,-655.67 h60
  text "TID #:" at 2248,-859 h60
  text ".TID" at 2793.5,-859 h60
  text "PLOT NAME =" at -228.5,-1064.34 h60
  text ".plot_File_Name" at 577,-1064.34 h60
  text "GENERATED    :" at 2250,-1064.34 h60
  text ".Print_Date" at 3119.5,-1064.34 h60
  text ".Print_Time" at 3848.5,-1064.34 h60
  text "TEXAS INSTRUMENTS" at 5113,-1064.34 h60
M6 Assembly Bottom:
  lines w10: -292.5,-727.33 6309.5,-727.33 ; -290.5,-930.67 6309.5,-930.67 ; 1115.5,-1140.5 1115.5,-937.67 ; 1737.5,-727.33 1737.5,-524 ; 2577.5,-727.33 2577.5,-524 ; 3844.5,-1134 3844.5,-524 ; 4733.5,-1134 6309,-1134 6309,-524 -292.5,-524 -292.5,-1134 2304.5,-1134 6309.5,-1134 6309.5,-524
  text "COMPONENTS MARKED 'DNP' SHOULD NOT BE POPULATED." at 6102,-318 h60
  text ".VariantName" at 5058,-434 h60
  text "ASSEMBLY VARIANT:" at 6097,-434 h60
  text ".VersionControl_RevNumber" at 1035.5,-656.17 h60
  text "SVN REV:" at 1541.5,-656.17 h60
  text ".PCB_Rev" at 2088,-656.17 h60
  text "REV:" at 2379.5,-656.17 h60
  text ".PRJ_Number" at 3224,-656.17 h60
  text "BOARD #:" at 3769.5,-656.17 h60
  text "PCB VIEWED FROM BOTTOM SIDE" at 6246,-656.17 h60
  text ".TID" at 3224,-859.5 h60
  text "TID #:" at 3769.5,-859.5 h60
  text "TEXAS INSTRUMENTS" at 904.5,-1064.84 h60
  text ".Print_Time" at 2169,-1064.84 h60
  text ".Print_Date" at 2898,-1064.84 h60
  text "GENERATED    :" at 3767.5,-1064.84 h60
  text ".plot_File_Name" at 5440.5,-1064.84 h60
  text "PLOT NAME =" at 6246,-1064.84 h60
M9 Title Sheet:
  drawing of 57 lines, arcs and shapes, not listed
  text "1" at 739.84,8036.5 h70
  text "2" at 3235.5,8036.5 h70
  text "3" at 5724.84,8036.5 h70
  text "4" at 8231.51,8036.5 h70
  text "5" at 10730.5,8036.5 h70
  text "6" at 13235.5,8036.5 h70
  text "A" at -416.5,6893.5 h70
  text "A" at 14383.5,6893.5 h70
  text "B" at -416.5,4513.5 h70
  text "B" at 14383.5,4513.5 h70
  text "C" at -416.5,2138.5 h70
  text "C" at 14383.5,2138.5 h70
  text "PROJECT TITLE:" at 11343.5,277.5 h45
  text ".PRJ_Title" at 11393.5,144.17 h70
  text "DESIGNED FOR:" at 11343.5,-23.5 h45
  text ".PRJ_Customer" at 11393.5,-163.5 h70
  text "D" at -416.5,-231.5 h70
  text "D" at 14383.5,-231.5 h70
  text "FILE NAME:" at 11343.5,-323.5 h45
  text ".PCB_File_Name_No_Path" at 11393.5,-443.5 h70
  text "Texas Instruments (TI) and/or its licensors do not warrant the accuracy or completeness of this specification" at 6374,-605.34 h45
  text "ENGINEER:" at 11343.5,-613.5 h45
  text "LAYOUT BY:" at 12848.5,-613.5 h45
  text "or any information contained therein. TI and/or its licensors do not warrant that this design will meet" at 6329.01,-718 h45
  text ".PRJ_Engineer" at 11393.5,-768.49 h70
  text ".PCB_Layout" at 12899,-768.49 h70
  text "the specifications, will be suitable for your application or fit for any particular purpose, or will operate in" at 6329.01,-830.67 h45
  text ".Layer_Name" at 577,-858.49 h60
  text "ALTIUM DESIGNER VERSION:" at 12848.5,-923.5 h45
  text "an implementation. TI and/or its licensors do not warrant that the design is production worthy. You should" at 6329.01,-943.33 h45
  text "completely validate and test your design implementation to confirm the system functionality for your application." at 6374,-1056 h45
  text ".print_Scale" at 11393.5,-1056.83 h70
  text ".Application_BuildNumber" at 12899,-1056.83 h70
  text "1" at 739.84,-1263.5 h70
  text "2" at 3235.5,-1263.5 h70
  text "3" at 5724.84,-1263.5 h70
  text "4" at 8231.51,-1263.5 h70
  text "5" at 10730.5,-1263.5 h70
  text "6" at 13235.5,-1263.5 h70
M10 Fab Notes:
  drawing of 189 lines, arcs and shapes, not listed
  text "DESIGN INFORMATION" at 12381.02,6028 h60
  text "MIN. TRACK WIDTH:" at 11736.46,5848 h60
  text "8" at 12832.7,5848 h60
  text "MIL" at 12987.46,5848 h60
  text "MIN. CLEARANCE:" at 11736.46,5716 h60
  text "0.2" at 12772.7,5716 h60
  text "mm" at 12987.46,5716 h60
  text "MIN. VIA PAD SIZE:" at 11736.46,5584 h60
  text "24" at 12802.71,5584 h60
  text "MIL" at 12987.46,5584 h60
  text "0.05mm (2MIL)" at 12431.46,5442.29 h60
  text "MINIMUM ANNULAR RING" at 11407.23,5438 h60
  text "EXTERNAL" at 13139.46,5438 h60
  text "PER" at 11607.23,5320 h60
  text "IPC-D-275 CLASS 2 LEVEL C" at 11827.23,5320 h60
  text "MIL, HOLES" at 13315.46,5207.71 h60
  text "+/-" at 12923,5207 h60
  text "+/-" at 13777,5207 h60
  text "REGISTRATION TOLERANCES:" at 11407.23,5202 h60
  text "METAL" at 12607,5202 h60
  text "5" at 13183.2,5202 h60
  text "3" at 14016.2,5202 h60
  text "MIL" at 14132.46,5202 h60
  text "+/-" at 13777,5089 h60
  text "HOLE SIZE TOLERANCE (UNLESS OTHERWISE SPECIFIED):" at 11407.23,5084 h60
  text "3" at 14016.2,5084 h60
  text "MIL" at 14132.46,5084 h60
  text "MATERIAL:" at 11332.46,4874.54 h60
  text "FR-4 High Tg" at 12318.9,4734.21 h60
  text "FR-408" at 11753.46,4725.64 h60
  text "OTHER" at 13241.46,4725.64 h60
  text "X" at 12164,4722 h60
  text "62 MIL (1.6mm) +/-10%" at 12073.56,4562.92 h60
  text "THICKNESS:" at 11407.23,4558.64 h60
  text "X" at 11945.4,4558.64 h60
  text "OTHER" at 13358.46,4558.64 h60
  text "TOLERANCE:" at 11407.23,4400.64 h60
  text "X" at 12246.53,4400.64 h60
  text "ANSI IPC-6012 TYPE 3 CLASS 2" at 12433.48,4400.64 h60
  text "OTHER +/-" at 12433.46,4244.64 h60
  text "BOW & TWIST:" at 11407.23,4087.64 h60
  text "X" at 12246.53,4087.64 h60
  text "ANSI IPC-6012 TYPE 3 CLASS 2" at 12433.48,4087.64 h60
  text "OTHER +/-" at 12433.46,3929.13 h60
  text "DRILLING:" at 11332.46,3790.64 h60
  text "REFERENCE:" at 11407.23,3673.64 h60
  text "X" at 12055.46,3673.64 h60
  text "AS SHOWN" at 12242.46,3673.64 h60
  text "X" at 12956.46,3673.64 h60
  text "NC_DRILL FILES" at 13093.46,3673.64 h60
  text "PTH MIN COPPER THICKNESS:" at 11407.23,3515.64 h60
  text "X" at 12757.46,3515.64 h60
  text "1MIL" at 12894.46,3515.64 h60
  text "OTHER" at 13391.46,3515.64 h60
  text "BOARD FINISH:" at 11332.46,3356.64 h60
  text "SILKSCREEN:" at 11487.68,3238.64 h60
  text "X" at 12436.46,3238.64 h60
  text "TOP" at 12562.46,3238.64 h60
  text "X" at 12946.46,3238.64 h60
  text "BOTTOM" at 13073.46,3238.64 h60
  text "SILKSCREEN COLOR:" at 11487.68,3071.64 h60
  text "X" at 12435.42,3071.64 h60
  text "WHITE" at 12562.46,3071.64 h60
  text "OTHER" at 13073.46,3071.64 h60
  text "X" at 12566.42,2912.44 h60
  text "GREEN" at 12693.46,2912.44 h60
  text "OTHER" at 13311.46,2912.44 h60
  text "SOLDER RESIST COLOR:" at 11487.68,2901.64 h60
  text "X" at 12566.42,2742.44 h60
  text "MATTE" at 12693.46,2742.44 h60
  text "SEMI-GLOSS" at 13311,2741.8 h60
  text "IMMERSION GOLD (ENIG)" at 12393.46,2553.92 h60
  text "ENEPIG" at 13731,2550.64 h60
  text "SURFACE FINISH:" at 11332.46,2549.64 h60
  text "X" at 12206.51,2549.64 h60
  text "IMM. TIN/SILVER OR EQUIV" at 11662,2392.64 h60
  text "OTHER" at 13093.46,2392.64 h60
  text "ARRAY/PANEL:" at 11332.46,2213.64 h60
  text "CUT AND TRIM PER M1 BOARD OUTLINE" at 12393.46,2209.35 h60
  text "N.C. ROUTE" at 12393.46,2057.64 h60
  text "X" at 13072.46,2057.64 h60
  text "V. SCORE" at 13259.46,2057.64 h60
  text "CERTIFICATION:" at 11332.46,1920.64 h60
  text "MATERIALS AND WORKMANSHIP FOR ALL PCBS" at 12057.46,1920.64 h60
  text "TO MEET OR EXCEED THE REQUIREMENTS OF:" at 12057.46,1822.64 h60
  text "X" at 11683.96,1686.13 h60
  text "ANSI IPC-A-600F CLASS ->" at 11822.96,1686.13 h60
  text "X" at 13462.02,1686.13 h60
  text "2" at 13580.96,1686.14 h60
  text "1" at 13265.96,1684.64 h60
  text "3" at 13934.96,1684.64 h60
  text "X" at 11686.02,1526.64 h60
  text "UL 94V-0" at 11822.96,1526.64 h60
  text "X" at 12498.02,1526.64 h60
  text "RoHS" at 12634.96,1526.64 h60
  text "OTHER" at 13279.36,1526.64 h60
  text "PER ORDER" at 13676.42,1526.64 h60
  text "ADDITIONAL REQUIREMENTS:" at 11332.46,1385.64 h60
  text "MICROSECTION:" at 11407.23,1270.64 h60
  text "YES" at 12312.96,1270.64 h60
  text "REQUIRED" at 13174.46,1114.49 h60
  text "BARE BOARD ELEC. TEST:" at 11407.23,1111.64 h60
  text "NONE" at 12712.96,1111.64 h60
  text "X" at 13047.46,1111.64 h60
  text "PER ORDER" at 13766.46,1111.64 h60
  text "MANUFACTURER'S UL:" at 11407.23,954.64 h60
  text "RAIL" at 12572.96,950.35 h60
  text "METAL" at 13064.77,950.35 h60
  text "X" at 13440,950 h60
  text "SILK" at 13576.46,950.35 h60
  text ".Layer_Name" at 577,-858.49 h60
M11 Gerber Information:
  lines w10: -292,-930.17 6308,-930.17 ; -292,-726.83 6310,-726.83 ; -292,-523.5 -292,-1133.5 3713,-1133.5 6310,-1133.5 6310,-523.5 -291.5,-523.5 -291.5,-1133.5 1284,-1133.5 ; 2173,-1133.5 2173,-523.5 ; 3440,-726.83 3440,-523.5 ; 4280,-726.83 4280,-523.5 ; 4902,-1140 4902,-937.17
  text "ALL ARTWORK VIEWED FROM TOP SIDE" at -228.5,-655.67 h60
  text "BOARD #:" at 2248,-655.67 h60
  text ".PRJ_Number" at 2793.5,-655.67 h60
  text "REV:" at 3638,-655.67 h60
  text ".PCB_Rev" at 3929.5,-655.67 h60
  text "SVN REV:" at 4476,-655.67 h60
  text ".VersionControl_RevNumber" at 4982,-655.67 h60
  text "LAYER NAME =" at -228.5,-858.49 h60
  text "TID #:" at 2248,-859 h60
  text ".TID" at 2793.5,-859 h60
  text "PLOT NAME =" at -228.5,-1064.34 h60
  text ".plot_File_Name" at 577,-1064.34 h60
  text "GENERATED    :" at 2250,-1064.34 h60
  text ".Print_Date" at 3119.5,-1064.34 h60
  text ".Print_Time" at 3848.5,-1064.34 h60
  text "TEXAS INSTRUMENTS" at 5113,-1064.34 h60
M12 Stackup:
  drawing of 191 lines, arcs and shapes, not listed
  text "Layer" at 9790.34,7830 h60
  text "Name" at 10200.26,7830 h60
  text "Material" at 11130,7830 h60
  text "Thickness" at 11989.77,7830 h60
  text "Constant" at 12639.6,7830 h60
  text "Board Layer Stack" at 13209.46,7830 h60
  text "1" at 9790.34,7710 h60
  text "Top Overlay" at 10200.26,7710 h60
  text "2" at 9790.34,7590 h60
  text "Top Solder" at 10200.26,7590 h60
  text "Solder Resist" at 11130,7590 h60
  text "0.40mil" at 11989.77,7590 h60
  text "3.5" at 12639.6,7590 h60
  text "3" at 9790.34,7470 h60
  text "Top Layer" at 10200.26,7470 h60
  text "Copper" at 11130,7470 h60
  text "2.80mil" at 11989.77,7470 h60
  text "4" at 9790.34,7350 h60
  text "Dielectric1" at 10200.26,7350 h60
  text "FR-4" at 11130,7350 h60
  text "56.40mil" at 11989.77,7350 h60
  text "4.8" at 12639.6,7350 h60
  text "5" at 9790.34,7230 h60
  text "Bottom Layer" at 10200.26,7230 h60
  text "Copper" at 11130,7230 h60
  text "2.80mil" at 11989.77,7230 h60
  text "6" at 9790.34,7110 h60
  text "Bottom Solder" at 10200.26,7110 h60
  text "Solder Resist" at 11130,7110 h60
  text "0.40mil" at 11989.77,7110 h60
  text "3.5" at 12639.6,7110 h60
  text "7" at 9790.34,6990 h60
  text "Bottom Overlay" at 10200.26,6990 h60
  text ".Layer_Name" at 577,-858.49 h60
M13 Component Bodies Top:
  text ".Layer_Name" at 577,-858.49 h60
M14 Component Bodies Bottom:
  text ".Layer_Name" at 577,-858.49 h60
M15 Courtyards Top:
  text ".Layer_Name" at 577,-858.49 h60
M16 Courtyards Bottom:
  text ".Layer_Name" at 577,-858.49 h60
Drill Drawing:
  drawing of 158 lines, arcs and shapes, not listed
  text "Symbol" at 5674.53,3363.05 h72
  text "Quantity" at 5984.9,3363.05 h72
  text "Finished Hole Size" at 6326.64,3363.05 h72
  text "Plated" at 6972.66,3363.05 h72
  text "Hole Type" at 7241.59,3363.05 h72
  text "4" at 5984.9,3238.84 h60
  text "141.73mil (3.600mm)" at 6326.64,3238.84 h60
  text "NPTH" at 6972.66,3238.84 h60
  text "Round" at 7241.59,3238.84 h60
  text "A" at 5667.3,3124.98 h41.4
  text "1" at 5984.9,3114.63 h60
  text "39.37mil (1.000mm)" at 6326.64,3114.63 h60
  text "NPTH" at 6972.66,3114.63 h60
  text "Slot" at 7241.59,3114.63 h60
  text "C" at 5667.3,3000.77 h41.4
  text "3" at 5984.9,2990.42 h60
  text "39.37mil (1.000mm)" at 6326.64,2990.42 h60
  text "NPTH" at 6972.66,2990.42 h60
  text "Slot" at 7241.59,2990.42 h60
  text "M" at 5667.3,2876.56 h41.4
  text "4" at 5984.9,2866.21 h60
  text "39.37mil (1.000mm)" at 6326.64,2866.21 h60
  text "NPTH" at 6972.66,2866.21 h60
  text "Slot" at 7241.59,2866.21 h60
  text "1" at 5984.9,2742 h60
  text "39.37mil (1.000mm)" at 6326.64,2742 h60
  text "NPTH" at 6972.66,2742 h60
  text "Slot" at 7241.59,2742 h60
  text "2" at 5984.9,2617.79 h60
  text "29.53mil (0.750mm)" at 6326.64,2617.79 h60
  text "PTH" at 6972.66,2617.79 h60
  text "Round" at 7241.59,2617.79 h60
  text "4" at 5984.9,2493.57 h60
  text "33.46mil (0.850mm)" at 6326.64,2493.57 h60
  text "PTH" at 6972.66,2493.57 h60
  text "Round" at 7241.59,2493.57 h60
  text "4" at 5984.9,2369.36 h60
  text "35.00mil (0.889mm)" at 6326.64,2369.36 h60
  text "PTH" at 6972.66,2369.36 h60
  text "Round" at 7241.59,2369.36 h60
  text "5" at 5984.9,2245.15 h60
  text "35.43mil (0.900mm)" at 6326.64,2245.15 h60
  text "PTH" at 6972.66,2245.15 h60
  text "Round" at 7241.59,2245.15 h60
  text "4" at 5984.9,2120.94 h60
  text "36.22mil (0.920mm)" at 6326.64,2120.94 h60
  text "PTH" at 6972.66,2120.94 h60
  text "Round" at 7241.59,2120.94 h60
  text "2" at 5984.9,1996.73 h60
  text "37.40mil (0.950mm)" at 6326.64,1996.73 h60
  text "PTH" at 6972.66,1996.73 h60
  text "Round" at 7241.59,1996.73 h60
  text "8" at 5984.9,1872.52 h60
  text "43.31mil (1.100mm)" at 6326.64,1872.52 h60
  text "PTH" at 6972.66,1872.52 h60
  text "Round" at 7241.59,1872.52 h60
  text "3" at 5984.9,1748.31 h60
  text "49.21mil (1.250mm)" at 6326.64,1748.31 h60
  text "PTH" at 6972.66,1748.31 h60
  text "Round" at 7241.59,1748.31 h60
  text "2" at 5984.9,1624.1 h60
  text "51.18mil (1.300mm)" at 6326.64,1624.1 h60
  text "PTH" at 6972.66,1624.1 h60
  text "Round" at 7241.59,1624.1 h60
  text "2" at 5984.9,1499.89 h60
  text "55.12mil (1.400mm)" at 6326.64,1499.89 h60
  text "PTH" at 6972.66,1499.89 h60
  text "Round" at 7241.59,1499.89 h60
  text "4" at 5984.9,1375.67 h60
  text "63.00mil (1.600mm)" at 6326.64,1375.67 h60
  text "PTH" at 6972.66,1375.67 h60
  text "Round" at 7241.59,1375.67 h60
  text "2" at 5984.9,1251.46 h60
  text "90.55mil (2.300mm)" at 6326.64,1251.46 h60
  text "PTH" at 6972.66,1251.46 h60
  text "Round" at 7241.59,1251.46 h60
  text "55 Total" at 5984.9,1127.25 h60
  text ".Layer_Name" at 577,-858.49 h60

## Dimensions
0,-400 to 1000,-400 on M2 Board Dimensions
0,2000 to 2700,2000 on M2 Board Dimensions
0,0 to 0,2000 on M2 Board Dimensions
2700,1700 to 2700,310 on M2 Board Dimensions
